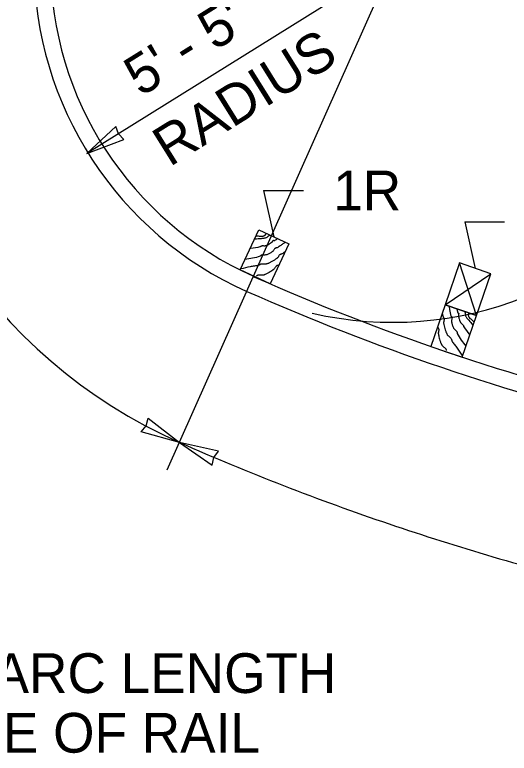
# Model space of a CAD drawing. Extents: x 1312564.2 to 1312581.5, y 1207298.4 to 1207352.6.
# Drawn here: x 1312566.145 to 1312567.136, y 1207300.702 to 1207302.182 of the extents above; entities that cross this region are included whole.
import ezdxf

# ---------------------------------------------------------------- set-up
doc = ezdxf.new("R2010")
doc.units = 0
for name, color, linetype in [('Level 13', 7, 'Continuous'), ('Level 14', 7, 'Continuous'), ('Level 15', 7, 'Continuous'), ('Level 20', 7, 'Continuous')]:
    doc.layers.add(name, color=color, linetype=linetype)

msp = doc.modelspace()

# ---------------------------------------------------------------- linework, layer by layer
at = {"layer": 'Level 13'}
for points in [[(1312566.656332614, 1207301.7406234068), (1312566.6540828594, 1207301.7390949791), (1312566.6535777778, 1207301.7387409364), (1312566.6530754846, 1207301.7383707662), (1312566.6500468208, 1207301.736079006), (1312566.647917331, 1207301.7348346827), (1312566.6456016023, 1207301.7341744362), (1312566.6384679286, 1207301.7333953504), (1312566.6265934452, 1207301.7320985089)], [(1312566.6491022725, 1207301.7439842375), (1312566.6481123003, 1207301.7424861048), (1312566.6470971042, 1207301.741038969), (1312566.645984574, 1207301.7397886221), (1312566.6453692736, 1207301.739282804), (1312566.645042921, 1207301.739067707), (1312566.6448745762, 1207301.7389706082), (1312566.64478905, 1207301.7389247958), (1312566.6447459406, 1207301.7389025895), (1312566.6447242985, 1207301.738891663), (1312566.644702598, 1207301.7388808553), (1312566.6443064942, 1207301.738698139), (1312566.64390023, 1207301.7385359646), (1312566.6430592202, 1207301.738269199), (1312566.6412772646, 1207301.7379377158), (1312566.6374255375, 1207301.7378566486), (1312566.6334032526, 1207301.7381204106), (1312566.6314081, 1207301.7382199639), (1312566.6294662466, 1207301.7382117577)], [(1312566.6868916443, 1207301.7264188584), (1312566.6822304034, 1207301.7229259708), (1312566.6794437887, 1207301.7208887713), (1312566.6766161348, 1207301.7189064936), (1312566.6737615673, 1207301.7169654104), (1312566.6708942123, 1207301.715051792), (1312566.6704924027, 1207301.714858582), (1312566.6700521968, 1207301.714760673), (1312566.6691066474, 1207301.71472659), (1312566.668157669, 1207301.7147012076), (1312566.667305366, 1207301.7144361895), (1312566.6668084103, 1207301.7140972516), (1312566.6663492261, 1207301.7137127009), (1312566.66552328, 1207301.7128313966), (1312566.6640948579, 1207301.7107924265), (1312566.6626858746, 1207301.7087134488), (1312566.6614408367, 1207301.707365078), (1312566.6609621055, 1207301.706988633), (1312566.6584416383, 1207301.7053008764), (1312566.6558210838, 1207301.703766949), (1312566.6530974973, 1207301.7024107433), (1312566.650267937, 1207301.7012561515), (1312566.6488924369, 1207301.7008838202), (1312566.647474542, 1207301.7007027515), (1312566.6445759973, 1207301.700659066), (1312566.6417011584, 1207301.700614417), (1312566.6403128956, 1207301.7004321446), (1312566.6389788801, 1207301.700058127), (1312566.638373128, 1207301.6996613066), (1312566.6378438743, 1207301.699103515), (1312566.6373033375, 1207301.6985715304), (1312566.6366637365, 1207301.6982521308), (1312566.6063264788, 1207301.6918819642)], [(1312566.6715938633, 1207301.733529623), (1312566.6652753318, 1207301.7292434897), (1312566.6649782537, 1207301.729123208), (1312566.6646496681, 1207301.7291148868), (1312566.663939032, 1207301.7292870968), (1312566.6632255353, 1207301.7294660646), (1312566.662591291, 1207301.729357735), (1312566.662360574, 1207301.729196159), (1312566.662149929, 1207301.729011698), (1312566.6617779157, 1207301.7285864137), (1312566.66115439, 1207301.7275964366), (1312566.6605456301, 1207301.7265844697), (1312566.6601920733, 1207301.7261316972), (1312566.6597765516, 1207301.7257471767), (1312566.6584333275, 1207301.7247475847), (1312566.6570686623, 1207301.7237690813), (1312566.654253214, 1207301.7219228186), (1312566.6497330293, 1207301.7196083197), (1312566.6489362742, 1207301.719294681), (1312566.6481253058, 1207301.7190056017), (1312566.6470500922, 1207301.7187465), (1312566.6459523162, 1207301.7186502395), (1312566.6437263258, 1207301.7187341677), (1312566.641521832, 1207301.7188332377), (1312566.639927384, 1207301.7186623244), (1312566.6396690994, 1207301.7185989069), (1312566.6394133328, 1207301.7185232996), (1312566.6386543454, 1207301.718150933), (1312566.6379352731, 1207301.717651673), (1312566.6372046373, 1207301.7171828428), (1312566.63641096, 1207301.7169017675), (1312566.6183772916, 1207301.7140168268)], [(1312566.6867464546, 1207301.707185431), (1312566.680298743, 1207301.702735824), (1312566.6794432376, 1207301.7023530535), (1312566.6784967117, 1207301.702156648), (1312566.6775469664, 1207301.7019674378), (1312566.6766818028, 1207301.7016062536), (1312566.6758191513, 1207301.70092768), (1312566.6750767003, 1207301.7001140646), (1312566.673801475, 1207301.6982453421), (1312566.6725542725, 1207301.6963273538), (1312566.6714556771, 1207301.6950534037), (1312566.6710332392, 1207301.6946873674), (1312566.666417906, 1207301.6912305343), (1312566.6615966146, 1207301.6880934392), (1312566.6565166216, 1207301.6853699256), (1312566.6538631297, 1207301.6841925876), (1312566.6525051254, 1207301.6836551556), (1312566.6511251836, 1207301.6831538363), (1312566.6494459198, 1207301.6827211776), (1312566.6477296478, 1207301.6825218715), (1312566.6442452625, 1207301.682519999), (1312566.640790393, 1207301.682541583), (1312566.6382898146, 1207301.6822082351), (1312566.6374834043, 1207301.6819799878), (1312566.6365388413, 1207301.6815283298), (1312566.6356393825, 1207301.6809361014), (1312566.6347287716, 1207301.680370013), (1312566.633750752, 1207301.6799967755), (1312566.6294545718, 1207301.6792081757), (1312566.625123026, 1207301.6785637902), (1312566.6207933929, 1207301.677897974), (1312566.6165029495, 1207301.6770450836), (1312566.598064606, 1207301.6727081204)], [(1312566.674508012, 1207301.6808561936), (1312566.6734593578, 1207301.680136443), (1312566.673048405, 1207301.679910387), (1312566.672603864, 1207301.6797532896), (1312566.6716576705, 1207301.6795565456), (1312566.6707080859, 1207301.6793673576), (1312566.6702593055, 1207301.6792197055), (1312566.6698424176, 1207301.6790068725), (1312566.6689788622, 1207301.6783293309), (1312566.6682359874, 1207301.6775161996), (1312566.6669609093, 1207301.6756473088), (1312566.6657144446, 1207301.6737284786), (1312566.6650073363, 1207301.672852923), (1312566.664193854, 1207301.6720879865), (1312566.6630559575, 1207301.6711996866), (1312566.6619068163, 1207301.6703282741), (1312566.6547405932, 1207301.6655197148), (1312566.6496585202, 1207301.662799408), (1312566.647011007, 1207301.66161285), (1312566.6456584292, 1207301.6610670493), (1312566.6442857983, 1207301.6605544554), (1312566.6426031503, 1207301.660143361), (1312566.64086381, 1207301.6600193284), (1312566.637315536, 1207301.6602093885), (1312566.6338419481, 1207301.66027852), (1312566.6321959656, 1207301.6600033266), (1312566.6306440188, 1207301.6593806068), (1312566.6289884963, 1207301.6584080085)], [(1312567.0150783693, 1207301.5983276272), (1312567.0160290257, 1207301.592581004), (1312567.0166325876, 1207301.5891823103), (1312567.017303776, 1207301.585794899), (1312567.0180228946, 1207301.5824186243), (1312567.018770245, 1207301.5790533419), (1312567.018926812, 1207301.578635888), (1312567.0191770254, 1207301.5782607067), (1312567.0198363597, 1207301.577582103), (1312567.0205041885, 1207301.5769074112), (1312567.0209364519, 1207301.5761265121), (1312567.021060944, 1207301.5755380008), (1312567.0211266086, 1207301.5749426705), (1312567.021113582, 1207301.5737348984), (1312567.0207349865, 1207301.571274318), (1312567.0203146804, 1207301.5687982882), (1312567.0202812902, 1207301.5669633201), (1312567.0203666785, 1207301.5663603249), (1312567.0210197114, 1207301.5633980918), (1312567.021851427, 1207301.560477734), (1312567.0228804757, 1207301.5576144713), (1312567.0241255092, 1207301.554823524), (1312567.0248614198, 1207301.5536032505), (1312567.0257602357, 1207301.5524917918), (1312567.0278234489, 1207301.5504554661), (1312567.0298688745, 1207301.5484348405), (1312567.0307454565, 1207301.5473430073), (1312567.0314502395, 1207301.546150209), (1312567.031613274, 1207301.5454446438), (1312567.0316097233, 1207301.5446757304), (1312567.0316321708, 1207301.5439176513), (1312567.0318732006, 1207301.543244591), (1312567.0493778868, 1207301.517661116)], [(1312567.0310450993, 1207301.5928825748), (1312567.0326440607, 1207301.5854167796), (1312567.0327754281, 1207301.5851244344), (1312567.0330069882, 1207301.5848911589), (1312567.0336393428, 1207301.584524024), (1312567.034278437, 1207301.5841597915), (1312567.034661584, 1207301.583642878), (1312567.034716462, 1207301.5833666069), (1312567.0347410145, 1207301.583087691), (1312567.0347155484, 1207301.5825232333), (1312567.0344811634, 1207301.5813769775), (1312567.0342209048, 1207301.5802250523), (1312567.034163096, 1207301.5796535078), (1312567.0341972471, 1207301.5790883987), (1312567.034476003, 1207301.5774374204), (1312567.0347848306, 1207301.575786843), (1312567.0355412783, 1207301.5725061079), (1312567.03720509, 1207301.5677081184), (1312567.0375636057, 1207301.5669305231), (1312567.0379493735, 1207301.5661608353), (1312567.0385467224, 1207301.565230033), (1312567.039272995, 1207301.564401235), (1312567.0409387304, 1207301.5629222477), (1312567.0425994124, 1207301.561469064), (1312567.0436327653, 1207301.5602428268), (1312567.0437754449, 1207301.560018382), (1312567.0439078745, 1207301.5597868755), (1312567.0441984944, 1207301.5589929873), (1312567.0443725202, 1207301.5581350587), (1312567.0445759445, 1207301.5572911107), (1312567.0449547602, 1207301.5565391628), (1312567.0559839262, 1207301.5419825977)], [(1312567.0018804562, 1207301.584336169), (1312567.0034596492, 1207301.57666296), (1312567.003812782, 1207301.575794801), (1312567.0043605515, 1207301.574998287), (1312567.0049156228, 1207301.574204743), (1312567.005290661, 1207301.573345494), (1312567.0054443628, 1207301.572258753), (1312567.0054178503, 1207301.5711576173), (1312567.0050463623, 1207301.5689259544), (1312567.0046205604, 1207301.566678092), (1312567.0045328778, 1207301.5649981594), (1312567.0045848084, 1207301.5644416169), (1312567.0055272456, 1207301.558752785), (1312567.0068395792, 1207301.5531524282), (1312567.0086248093, 1207301.5476718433), (1312567.0097269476, 1207301.5449862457), (1312567.0103360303, 1207301.5436588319), (1312567.0109859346, 1207301.542342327), (1312567.0118995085, 1207301.540868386), (1312567.0130012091, 1207301.539537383), (1312567.0155164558, 1207301.5371260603), (1312567.018026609, 1207301.5347520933), (1312567.0196020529, 1207301.5327818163), (1312567.0200266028, 1207301.5320592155), (1312567.0203964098, 1207301.5310797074), (1312567.0206364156, 1207301.53002987), (1312567.020902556, 1207301.528991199), (1312567.0213507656, 1207301.5280451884), (1312567.02390818, 1207301.5245041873), (1312567.0265908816, 1207301.5210428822), (1312567.0292573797, 1207301.5175674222), (1312567.031766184, 1207301.5139839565), (1312567.0420833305, 1207301.4980987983)], [(1312567.046973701, 1207301.5874505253), (1312567.0475414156, 1207301.584790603), (1312567.0476613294, 1207301.5841855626), (1312567.0477680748, 1207301.5835708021), (1312567.0483703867, 1207301.5798208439), (1312567.049047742, 1207301.5774492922), (1312567.0502635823, 1207301.5753707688), (1312567.054876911, 1207301.5698740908), (1312567.0625561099, 1207301.5607244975)], [(1312567.0545202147, 1207301.5848769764), (1312567.0541990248, 1207301.5831102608), (1312567.0539313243, 1207301.581362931), (1312567.053870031, 1207301.5796904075), (1312567.053964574, 1207301.5788995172), (1312567.0540515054, 1207301.5785184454), (1312567.0541059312, 1207301.5783318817), (1312567.054136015, 1207301.57823964), (1312567.054151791, 1207301.5781937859), (1312567.0541598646, 1207301.5781709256), (1312567.0541680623, 1207301.5781481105), (1312567.0543277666, 1207301.5777421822), (1312567.0545090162, 1207301.577344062), (1312567.0549319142, 1207301.5765697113), (1312567.0559896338, 1207301.5750978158), (1312567.0587154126, 1207301.5723752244), (1312567.0618028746, 1207301.5697837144), (1312567.063312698, 1207301.5684756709), (1312567.064709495, 1207301.5671266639)], [(1312566.9925088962, 1207301.5568555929), (1312566.9927684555, 1207301.5556104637), (1312566.992908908, 1207301.555162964), (1312566.9931213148, 1207301.5547420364), (1312566.9936686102, 1207301.5539455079), (1312566.9942235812, 1207301.5531520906), (1312566.9944455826, 1207301.552735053), (1312566.9945994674, 1207301.5522929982), (1312566.9947545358, 1207301.551206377), (1312566.9947286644, 1207301.5501052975), (1312566.9943569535, 1207301.5478736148), (1312566.9939300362, 1207301.5456256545), (1312566.9938351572, 1207301.5445042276), (1312566.9938936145, 1207301.5433891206), (1312566.994101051, 1207301.5419605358), (1312566.994328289, 1207301.54053637), (1312566.9961781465, 1207301.5321069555), (1312566.9979670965, 1207301.5266272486), (1312566.9990585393, 1207301.5239391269), (1312566.9996579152, 1207301.5226094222), (1312567.0002947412, 1207301.521289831), (1312567.0012256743, 1207301.5198291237), (1312567.0023960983, 1207301.5185365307), (1312567.0050902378, 1207301.5162196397), (1312567.007646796, 1207301.5138670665), (1312567.0086452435, 1207301.5125298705), (1312567.0093354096, 1207301.51100672), (1312567.0098583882, 1207301.5091592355)]]:
    msp.add_spline(points, degree=3, dxfattribs=at)
at = {"layer": 'Level 14'}
for p, q in [((1312567.0703041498, 1207301.5794942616), (1312567.0360875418, 1207301.6846428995)), ((1312567.0075297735, 1207301.6009018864), (1312567.0988619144, 1207301.6632352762))]:
    msp.add_line(p, q, dxfattribs=at)
at = {"layer": 'Level 15'}
for p, q in [((1312566.926653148, 1207302.3395780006), (1312566.449579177, 1207301.269620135)), ((1312566.9031858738, 1207302.2868279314), (1312566.2891465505, 1207301.9039358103)), ((1312566.643651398, 1207301.8300050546), (1312566.6640518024, 1207301.7370353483)), ((1312566.643651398, 1207301.8300050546), (1312566.7233800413, 1207301.8300050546)), ((1312567.0470743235, 1207301.7669087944), (1312567.067474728, 1207301.673939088)), ((1312567.0470743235, 1207301.7669087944), (1312567.1268029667, 1207301.7669087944))]:
    msp.add_line(p, q, dxfattribs=at)
for points in [[(1312566.2891465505, 1207301.9039358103), (1312566.3637685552, 1207301.9323566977), (1312566.3525589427, 1207301.9434774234), (1312566.3475057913, 1207301.9584370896)], [(1312566.6568300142, 1207301.642824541), (1312566.5966856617, 1207301.6707810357), (1312566.633979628, 1207301.7510135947), (1312566.6941239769, 1207301.7230571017)], [(1312567.0075297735, 1207301.6009018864), (1312567.0703041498, 1207301.5794942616), (1312567.0988619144, 1207301.6632352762), (1312567.0360875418, 1207301.6846428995)], [(1312566.9789720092, 1207301.5171608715), (1312567.0417463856, 1207301.495753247), (1312567.0703041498, 1207301.5794942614), (1312567.0075297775, 1207301.6009018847)], [(1312566.4752556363, 1207301.3247560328), (1312566.3983895, 1207301.3463844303), (1312566.4085588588, 1207301.3584637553), (1312566.4122528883, 1207301.3738156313)], [(1312566.4752556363, 1207301.3247560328), (1312566.5408386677, 1207301.2792032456), (1312566.5436904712, 1207301.2947336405), (1312566.553186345, 1207301.3073492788)]]:
    msp.add_lwpolyline(points, close=True, dxfattribs=at)
for centre, radius, start, end in [((1312566.9019803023, 1207302.2843292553), 1.0501784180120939, 113.8898637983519, 246.02516281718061), ((1312566.9019803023, 1207302.2843292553), 0.7185570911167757, 257.0480322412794, 104.14729778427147), ((1312566.9019803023, 1207302.2843292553), 0.7185570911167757, 113.93888658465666, 246.02516281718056), ((1312566.9019803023, 1207302.2843292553), 0.6853949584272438, 113.93888658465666, 246.02516281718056), ((1312568.5257445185, 1207305.966142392), 4.710058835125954, 246.18812144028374, 266.40190679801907), ((1312568.5284006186, 1207305.9686885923), 4.745929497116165, 246.1577968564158, 266.37158221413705), ((1312568.5406376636, 1207306.0198805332), 5.129327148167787, 246.25533906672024, 251.2923504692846), ((1312568.5279260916, 1207305.9539346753), 5.0627964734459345, 251.18923592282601, 256.1281632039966)]:
    msp.add_arc(centre, radius, start, end, dxfattribs=at)

# ---------------------------------------------------------------- texts
at = {"layer": 'Level 20'}
for s, p in [('5\' - 5"', (1312566.3974370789, 1207302.016906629)), ('RADIUS ', (1312566.4551207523, 1207301.8762902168))]:
    msp.add_text(s, height=0.07972865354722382, rotation=31.94613333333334, dxfattribs=at).set_placement(p)
for s, p in [('1R', (1312566.7831765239, 1207301.7901407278)), ('12\' - 6" ARC LENGTH', (1312565.7419399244, 1207300.8225272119)), ('AT FACE OF RAIL', (1312565.7419399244, 1207300.7029342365))]:
    msp.add_text(s, height=0.07972865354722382, dxfattribs=at).set_placement(p)

doc.saveas('drawing.dxf')
